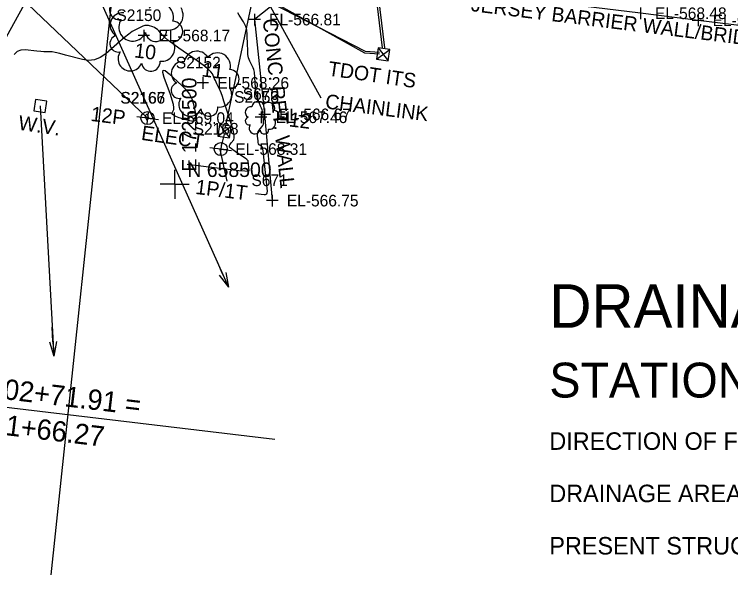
# Model space of a CAD drawing. Extents: x 1724534 to 1727318, y 657156 to 660047.
# Drawn here: x 1725444.8 to 1725691.4, y 658365.5 to 658558.5 of the extents above; entities that cross this region are included whole.
import ezdxf

# ---------------------------------------------------------------- set-up
doc = ezdxf.new("R2010")
doc.units = 0
for name, color, linetype in [('SURVEY - CENTERLINE - Preliminary Text', 7, 'Continuous'), ('SURVEY - CONTOURS - Intermediate with optional Text', 7, 'Continuous'), ('SURVEY - CONTROL - Grid', 7, 'Continuous'), ('SURVEY - CONTROL - Grid Text', 7, 'Continuous'), ('SURVEY - DRAINAGE - Area Shapes Text', 7, 'Continuous'), ('SURVEY - DRAINAGE - Storm Sewer', 7, 'Continuous'), ('SURVEY - DRAINAGE - Storm Sewer Text', 7, 'Continuous'), ('SURVEY - NON-TRANSPORTATION - Features', 7, 'Continuous'), ('SURVEY - NON-TRANSPORTATION - Features - Points - Elevations', 7, 'Continuous'), ('SURVEY - NON-TRANSPORTATION - Features - Points - Locators', 7, 'Continuous'), ('SURVEY - NON-TRANSPORTATION - Features - Points - Numbers', 7, 'Continuous'), ('SURVEY - NON-TRANSPORTATION - Features Text', 7, 'Continuous'), ('SURVEY - ROADSIDE BARRIERS - Points - Elevations', 7, 'Continuous'), ('SURVEY - ROADSIDE BARRIERS - Points - Locators', 7, 'Continuous'), ('SURVEY - ROADSIDE BARRIERS with Text', 7, 'Continuous'), ('SURVEY - UTILITIES - Electric (Underground) with Text', 7, 'Continuous'), ('SURVEY - UTILITIES - Fiber Optic Cable (Underground) with Text', 7, 'Continuous'), ('SURVEY - UTILITIES - Overhead Wire Crossings', 7, 'Continuous'), ('SURVEY - UTILITIES - Poles and Miscellaneous - Points - Elevations', 7, 'Continuous'), ('SURVEY - UTILITIES - Poles and Miscellaneous - Points - Locators', 7, 'Continuous'), ('SURVEY - UTILITIES - Poles and Miscellaneous - Points - Numbers', 7, 'Continuous'), ('SURVEY - UTILITIES - Poles and Miscellaneous with Text', 7, 'Continuous'), ('SURVEY - UTILITIES - Water with Text', 7, 'Continuous'), ('SURVEY - VEGETATION - Features - Points - Elevations', 7, 'Continuous'), ('SURVEY - VEGETATION - Features - Points - Locators', 7, 'Continuous'), ('SURVEY - VEGETATION - Features - Points - Numbers', 7, 'Continuous'), ('SURVEY - VEGETATION - Features with Text', 7, 'Continuous')]:
    doc.layers.add(name, color=color, linetype=linetype)

msp = doc.modelspace()

# ---------------------------------------------------------------- linework, layer by layer
at = {"layer": 'SURVEY - CENTERLINE - Preliminary Text'}
msp.add_line((1725332.93, 658436.26), (1725534.5, 658412.24), dxfattribs=at)
at = {"layer": 'SURVEY - CONTOURS - Intermediate with optional Text'}
for points in [[(1725527.79, 658496.86), (1725530.76, 658496.49), (1725531.31, 658496.5), (1725531.68, 658496.68), (1725531.88, 658497.04), (1725531.9, 658497.56), (1725530.43, 658511.53), (1725530.34, 658512.08), (1725530.22, 658512.51), (1725530.06, 658512.83), (1725529.86, 658513.03), (1725529.26, 658513.42), (1725529.06, 658513.62), (1725528.9, 658513.94), (1725528.77, 658514.37), (1725528.68, 658514.91), (1725528.49, 658516.51), (1725528.47, 658517.09), (1725528.56, 658517.63), (1725528.75, 658518.14), (1725529.05, 658518.6), (1725530, 658519.8), (1725530.3, 658520.25), (1725530.51, 658520.69), (1725530.61, 658521.14), (1725530.62, 658521.58), (1725530.4, 658523.86), (1725530.31, 658524.8), (1725530.25, 658525.12), (1725530.1, 658525.58), (1725529.88, 658526.18), (1725529.58, 658526.92), (1725528.68, 658529.07), (1725528.38, 658529.82), (1725528.15, 658530.48), (1725528.01, 658531.04), (1725527.94, 658531.51), (1725527.42, 658538.54), (1725527.35, 658539.03), (1725527.21, 658539.55), (1725527, 658540.12), (1725526.72, 658540.72), (1725525.89, 658542.39), (1725525.61, 658543), (1725525.41, 658543.58), (1725525.28, 658544.12), (1725525.22, 658544.63), (1725525.17, 658545.95), (1725525.14, 658546.45), (1725525.12, 658546.95), (1725525.1, 658547.47), (1725525.08, 658547.99), (1725525.02, 658549.39), (1725525, 658549.91), (1725524.97, 658550.45), (1725524.95, 658550.99), (1725524.93, 658551.55), (1725524.86, 658553.03), (1725524.77, 658553.62), (1725524.54, 658554.29), (1725524.18, 658555.04), (1725523.69, 658555.87), (1725522.19, 658558.17), (1725521.74, 658559.05)], [(1725504.32, 658506.95), (1725519.3, 658505.11), (1725522.1, 658504.78), (1725524.1, 658504.59), (1725525.3, 658504.54), (1725525.68, 658504.62), (1725525.33, 658508.01), (1725525.19, 658508.21), (1725524.83, 658508.54), (1725524.23, 658508.99), (1725523.39, 658509.56), (1725520.85, 658511.23), (1725520.01, 658511.8), (1725519.41, 658512.25), (1725519.04, 658512.57), (1725518.9, 658512.77), (1725518.86, 658513.15), (1725518.88, 658513.33), (1725518.99, 658513.57), (1725519.18, 658513.87), (1725519.46, 658514.25), (1725520.31, 658515.32), (1725520.5, 658515.95), (1725520.43, 658517.04), (1725520.1, 658518.59), (1725519.52, 658520.6), (1725517.61, 658526.57), (1725516.96, 658528.6), (1725516.4, 658530.23), (1725515.95, 658531.45), (1725515.61, 658532.27), (1725514.84, 658533.9), (1725514.56, 658534.52), (1725514.28, 658535.13), (1725514, 658535.74), (1725513.72, 658536.35), (1725513, 658537.97), (1725512.47, 658538.71), (1725511.41, 658539.71), (1725509.83, 658540.97), (1725507.72, 658542.5), (1725501.41, 658546.9), (1725499.28, 658548.42), (1725497.63, 658549.66), (1725496.45, 658550.62), (1725495.76, 658551.31), (1725494.53, 658552.78), (1725494.06, 658553.28), (1725493.56, 658553.68), (1725493.03, 658553.98), (1725492.47, 658554.19), (1725490.96, 658554.61), (1725490.37, 658554.69), (1725489.73, 658554.64), (1725489.04, 658554.46), (1725488.3, 658554.13), (1725486.26, 658553.09), (1725485.36, 658552.55), (1725484.2, 658551.71), (1725482.78, 658550.57), (1725481.1, 658549.14), (1725476.25, 658544.91), (1725474.39, 658543.59), (1725472.43, 658542.82), (1725470.38, 658542.6), (1725468.23, 658542.91), (1725462.39, 658544.48), (1725460.42, 658544.99), (1725458.91, 658545.35), (1725457.86, 658545.56), (1725457.27, 658545.62), (1725456.29, 658545.57), (1725455.78, 658545.58), (1725454.99, 658545.62), (1725453.9, 658545.71), (1725452.53, 658545.84), (1725448.48, 658546.23), (1725447.06, 658546.16), (1725445.81, 658545.66), (1725444.74, 658544.71)], [(1725496.39, 658536.76), (1725495.9, 658538.47), (1725496.02, 658539.26), (1725496.74, 658539.12), (1725498.07, 658538.06), (1725502.43, 658533.99), (1725503.9, 658532.47), (1725505.05, 658530.96), (1725505.87, 658529.45), (1725506.38, 658527.94), (1725507.29, 658523.94), (1725507.41, 658522.68), (1725507.11, 658521.9), (1725506.37, 658521.6), (1725505.2, 658521.78), (1725501.52, 658522.9), (1725500.34, 658523.32), (1725499.55, 658523.74), (1725499.15, 658524.17), (1725499.15, 658524.6), (1725499.68, 658525.74), (1725499.76, 658526.39), (1725499.58, 658527.48), (1725499.16, 658529), (1725498.5, 658530.95), (1725496.39, 658536.76)], [(1725490.89, 658522.57), (1725490.95, 658522.75), (1725490.97, 658522.93), (1725490.96, 658523.12), (1725490.91, 658523.31), (1725490.73, 658523.82), (1725490.65, 658523.97), (1725490.55, 658524.05), (1725490.44, 658524.05), (1725490.3, 658523.98), (1725489.93, 658523.69), (1725489.82, 658523.56), (1725489.78, 658523.39), (1725489.81, 658523.19), (1725489.9, 658522.95), (1725490.25, 658522.26), (1725490.37, 658522.06), (1725490.48, 658521.96), (1725490.58, 658521.98), (1725490.67, 658522.1), (1725490.89, 658522.57)]]:
    msp.add_lwpolyline(points, dxfattribs=at)
at = {"layer": 'SURVEY - CONTROL - Grid'}
for q in [(1725500, 658505), (1725495, 658500), (1725505, 658500), (1725500, 658495)]:
    msp.add_line((1725500, 658500), q, dxfattribs=at)
at = {"layer": 'SURVEY - DRAINAGE - Storm Sewer'}
for p, q in [((1725462.98, 658588.87), (1725518.53, 658464.57)), ((1725516.49, 658469.14), (1725514.45, 658473.7)), ((1725515.35, 658468.63), (1725518.53, 658464.57)), ((1725516.49, 658469.14), (1725518.53, 658464.57)), ((1725516.49, 658469.14), (1725518.53, 658464.57)), ((1725517.63, 658469.65), (1725518.53, 658464.57))]:
    msp.add_line(p, q, dxfattribs=at)
at = {"layer": 'SURVEY - DRAINAGE - Storm Sewer Text'}
msp.add_line((1725436.6, 658540.79), (1725462.98, 658588.87), dxfattribs=at)
at = {"layer": 'SURVEY - NON-TRANSPORTATION - Features'}
msp.add_lwpolyline([(1725539.44, 658572.34), (1725532.93, 658561.06), (1725527.49, 658556.7)], dxfattribs=at)
at = {"layer": 'SURVEY - NON-TRANSPORTATION - Features - Points - Locators'}
for p, q in [((1725527.49, 658558.7), (1725527.49, 658554.7)), ((1725527.49, 658558.7), (1725527.49, 658554.7)), ((1725529.49, 658556.7), (1725525.49, 658556.7)), ((1725529.49, 658556.7), (1725525.49, 658556.7)), ((1725530.93, 658526.05), (1725530.93, 658522.05)), ((1725532.93, 658524.05), (1725528.93, 658524.05)), ((1725533.59, 658496.36), (1725533.59, 658492.36)), ((1725535.59, 658494.36), (1725531.59, 658494.36))]:
    msp.add_line(p, q, dxfattribs=at)
at = {"layer": 'SURVEY - NON-TRANSPORTATION - Features Text'}
msp.add_line((1725532.93, 658561.06), (1725550.31, 658529.75), dxfattribs=at)
at = {"layer": 'SURVEY - ROADSIDE BARRIERS - Points - Locators'}
for p, q in [((1725660.28, 658560.86), (1725660.28, 658556.86)), ((1725682.13, 658556.43), (1725678.13, 658556.43)), ((1725680.13, 658558.43), (1725680.13, 658554.43))]:
    msp.add_line(p, q, dxfattribs=at)
at = {"layer": 'SURVEY - ROADSIDE BARRIERS with Text'}
for points in [[(1725762.72, 658545.48), (1725760.68, 658546.18), (1725739.67, 658549.03), (1725719.83, 658551.53), (1725699.98, 658553.97), (1725680.13, 658556.43), (1725660.28, 658558.86), (1725640.43, 658561.3), (1725620.59, 658563.76), (1725600.74, 658566.22), (1725580.89, 658568.65), (1725561.04, 658571.09), (1725541.17, 658573.41), (1725539.63, 658573.41), (1725538.14, 658573.13)], [(1725527.49, 658556.7), (1725530.93, 658524.05), (1725533.59, 658494.36)]]:
    msp.add_lwpolyline(points, dxfattribs=at)
at = {"layer": 'SURVEY - UTILITIES - Electric (Underground) with Text'}
for p, q in [((1725526.16, 658561.18), (1725517.23, 658519.23)), ((1725517.04, 658517.25), (1725515.97, 658513.06))]:
    msp.add_line(p, q, dxfattribs=at)
for points in [[(1725557.51, 658671.14), (1725558.43, 658655.23), (1725571.36, 658547)], [(1725570.47, 658545.32), (1725565.67, 658545.65), (1725533.36, 658562.34), (1725527.6, 658562.48)]]:
    msp.add_lwpolyline(points, dxfattribs=at)
at = {"layer": 'SURVEY - UTILITIES - Fiber Optic Cable (Underground) with Text'}
for points in [[(1725558.07, 658671.32), (1725558.96, 658656.48), (1725572.24, 658547)], [(1725570.54, 658544.83), (1725565.5, 658545.17), (1725533.56, 658562.95), (1725528.58, 658563.31), (1725528.95, 658565.81)]]:
    msp.add_lwpolyline(points, dxfattribs=at)
at = {"layer": 'SURVEY - UTILITIES - Overhead Wire Crossings'}
for p, q in [((1725512.62, 658889.98), (1725457.38, 658365.55)), ((1725320.87, 658684.66), (1725490.65, 658522.77))]:
    msp.add_line(p, q, dxfattribs=at)
at = {"layer": 'SURVEY - UTILITIES - Poles and Miscellaneous - Points - Locators'}
for p, q in [((1725490.89, 658524.75), (1725490.41, 658520.78)), ((1725492.64, 658522.52), (1725488.67, 658523.01)), ((1725517.84, 658511.87), (1725513.87, 658512.35)), ((1725516.1, 658514.09), (1725515.61, 658510.12))]:
    msp.add_line(p, q, dxfattribs=at)
at = {"layer": 'SURVEY - UTILITIES - Poles and Miscellaneous with Text'}
for p, q in [((1725569.51, 658543.01), (1725574.04, 658546.4)), ((1725570.08, 658546.97), (1725573.47, 658542.44)), ((1725571.77, 658544.7), (1725571.77, 658544.7)), ((1725490.65, 658522.77), (1725486.93, 658523.22)), ((1725490.65, 658522.77), (1725494.37, 658522.31)), ((1725514.88, 658516.59), (1725519.41, 658519.97)), ((1725515.45, 658520.55), (1725518.84, 658516.01)), ((1725517.15, 658518.28), (1725517.15, 658518.28)), ((1725515.85, 658512.11), (1725512.13, 658512.56)), ((1725515.57, 658511.97), (1725517.91, 658501.05)), ((1725515.85, 658512.11), (1725519.58, 658511.65))]:
    msp.add_line(p, q, dxfattribs=at)
for points in [[(1725570.08, 658546.97), (1725569.51, 658543.01), (1725573.47, 658542.44), (1725574.04, 658546.4), (1725570.08, 658546.97)], [(1725515.45, 658520.55), (1725514.88, 658516.59), (1725518.84, 658516.01), (1725519.41, 658519.97), (1725515.45, 658520.55)]]:
    msp.add_lwpolyline(points, dxfattribs=at)
for centre in [(1725490.65, 658522.77), (1725515.85, 658512.11)]:
    msp.add_circle(centre, 2.25, dxfattribs=at)
at = {"layer": 'SURVEY - UTILITIES - Water with Text'}
for p, q in [((1725453.74, 658526.97), (1725453.74, 658526.97)), ((1725453.74, 658526.97), (1725458.36, 658440.78)), ((1725458.09, 658445.77), (1725457.82, 658450.77)), ((1725456.88, 658445.71), (1725458.36, 658440.78)), ((1725458.09, 658445.77), (1725458.36, 658440.78)), ((1725458.09, 658445.77), (1725458.36, 658440.78)), ((1725459.3, 658445.84), (1725458.36, 658440.78))]:
    msp.add_line(p, q, dxfattribs=at)
msp.add_lwpolyline([(1725452.05, 658529.23), (1725451.48, 658525.27), (1725455.44, 658524.7), (1725456.01, 658528.66), (1725452.05, 658529.23)], dxfattribs=at)
at = {"layer": 'SURVEY - VEGETATION - Features - Points - Locators'}
for p, q in [((1725491.38, 658551.2), (1725487.38, 658551.2)), ((1725489.38, 658553.2), (1725489.38, 658549.2)), ((1725509.68, 658536.88), (1725509.68, 658532.88)), ((1725511.68, 658534.88), (1725507.68, 658534.88)), ((1725529.73, 658525.06), (1725529.73, 658521.06)), ((1725531.73, 658523.06), (1725527.73, 658523.06))]:
    msp.add_line(p, q, dxfattribs=at)
at = {"layer": 'SURVEY - VEGETATION - Features with Text'}
for centre, radius in [((1725489.58, 658551.28), 0.147), ((1725509.86, 658534.95), 0.137), ((1725529.83, 658523.1), 0.0685)]:
    msp.add_circle(centre, radius, dxfattribs=at)
for centre, radius, start, end in [((1725480.84, 658559.94), 3.27, 105.0317, 283.7773), ((1725494.82, 658557.51), 4.76, 342.8641, 138.7026), ((1725481.96, 658554.81), 4.21, 82.9155, 239.7044), ((1725497.76, 658558.18), 5.13, 262.9581, 29.8037), ((1725485.52, 658554.04), 4.76, 145.0523, 338.472), ((1725499.25, 658552.6), 3.51, 273.117, 88.1173), ((1725493.53, 658552.77), 3.62, 187.671, 4.9902), ((1725480.58, 658548.4), 2.89, 105.0317, 283.7773), ((1725495.52, 658546.84), 4.52, 262.9581, 29.8037), ((1725484.71, 658543.19), 4.2, 145.0523, 338.472), ((1725507.62, 658541.33), 4.47, 31.9683, 169.4925), ((1725514.76, 658540.77), 4.44, 342.8641, 138.7026), ((1725491.78, 658542.07), 3.19, 187.671, 4.9902), ((1725502.75, 658538.25), 3.92, 82.9155, 239.7044), ((1725518.89, 658536.18), 3.28, 273.117, 88.1173), ((1725501.47, 658532.26), 2.69, 105.0317, 283.7773), ((1725515.41, 658530.81), 4.22, 262.9581, 29.8037), ((1725505.32, 658527.4), 3.92, 145.0523, 338.472), ((1725511.92, 658526.36), 2.98, 187.671, 4.9902), ((1725526.27, 658524.75), 1.96, 82.9155, 239.7044), ((1725528.71, 658526.29), 2.24, 31.9683, 169.4925), ((1725532.27, 658526), 2.22, 342.8641, 138.7026), ((1725534.34, 658523.71), 1.64, 273.117, 88.1173), ((1725525.63, 658521.75), 1.35, 105.0317, 283.7773), ((1725532.6, 658521.03), 2.11, 262.9581, 29.8037), ((1725527.56, 658519.32), 1.96, 145.0523, 338.472), ((1725530.85, 658518.8), 1.49, 187.671, 4.9902)]:
    msp.add_arc(centre, radius, start, end, dxfattribs=at)

# ---------------------------------------------------------------- texts
at = {"layer": 'SURVEY - CENTERLINE - Preliminary Text'}
for s, p in [('MURPHY ROAD STA. 102+71.91 =', (1725340.19, 658438.04)), ('I-440 OFF RAMP STA. 21+66.27', (1725338.74, 658425.87))]:
    msp.add_text(s, height=7, rotation=353.2033, dxfattribs=at).set_placement(p)
at = {"layer": 'SURVEY - CONTROL - Grid Text'}
msp.add_text(' E 1725500 ', height=5, rotation=90, dxfattribs=at).set_placement((1725507.5, 658502.5))
msp.add_text(' N 658500 ', height=5, dxfattribs=at).set_placement((1725502.5, 658502.5))
at = {"layer": 'SURVEY - DRAINAGE - Area Shapes Text'}
for s, height, p in [('DRAINAGE DATA FOR PIPE', 15, (1725628.96, 658450.56)), ('STATION 103+01.90           ', 12, (1725628.96, 658426.56)), ('DIRECTION OF FLOW LEFT                   ', 6.0198, (1725628.96, 658408.54)), ('DRAINAGE AREA 0.299 AC        ROLLING', 6.0198, (1725628.96, 658390.52)), ('PRESENT STRUCTURE: 18"RCP                      ', 6.0198, (1725628.96, 658372.5))]:
    msp.add_text(s, height=height, dxfattribs=at).set_placement(p)
at = {"layer": 'SURVEY - NON-TRANSPORTATION - Features - Points - Elevations'}
for s, p in [('EL-566.81', (1725532.49, 658554.7)), ('EL-566.81', (1725532.49, 658554.7)), ('EL-566.67', (1725535.93, 658522.05)), ('EL-566.75', (1725538.59, 658492.36))]:
    msp.add_text(s, height=4, dxfattribs=at).set_placement(p)
at = {"layer": 'SURVEY - NON-TRANSPORTATION - Features - Points - Numbers'}
for s, p in [('S670', (1725523.42, 658529.05)), ('S671', (1725526.41, 658499.36))]:
    msp.add_text(s, height=4, dxfattribs=at).set_placement(p)
at = {"layer": 'SURVEY - NON-TRANSPORTATION - Features Text'}
msp.add_text('CHAINLINK', height=5, rotation=352.8338, dxfattribs=at).set_placement((1725551.6, 658526.13))
at = {"layer": 'SURVEY - ROADSIDE BARRIERS - Points - Elevations'}
for s, p in [('EL-568.48', (1725665.28, 658556.86)), ('EL-568.77', (1725685.13, 658554.43))]:
    msp.add_text(s, height=4, dxfattribs=at).set_placement(p)
at = {"layer": 'SURVEY - ROADSIDE BARRIERS with Text'}
for s, rotation, p in [('JERSEY BARRIER WALL/BRIDGE', 352.94, (1725601.83, 658559.64)), ('CONC. RET. WALL', 276.0056, (1725530.3, 658556.78))]:
    msp.add_text(s, height=5, rotation=rotation, dxfattribs=at).set_placement(p)
at = {"layer": 'SURVEY - UTILITIES - Poles and Miscellaneous - Points - Elevations'}
for s, p in [('EL-569.04', (1725495.65, 658520.77)), ('EL-569.04', (1725495.65, 658520.77)), ('EL-568.31', (1725520.85, 658510.11))]:
    msp.add_text(s, height=4, dxfattribs=at).set_placement(p)
at = {"layer": 'SURVEY - UTILITIES - Poles and Miscellaneous - Points - Numbers'}
for s, p in [('S2166', (1725481.25, 658527.77)), ('S2167', (1725481.36, 658527.77)), ('S2168', (1725506.52, 658517.11))]:
    msp.add_text(s, height=4, dxfattribs=at).set_placement(p)
at = {"layer": 'SURVEY - UTILITIES - Poles and Miscellaneous with Text'}
for s, rotation, p in [('TDOT ITS', 351.7546, (1725552.56, 658537.46)), ('12P', 352.8641, (1725470.9, 658521.83)), ('ELECT', 351.7546, (1725488.28, 658515.31)), ('1P/1T', 352.8641, (1725506.95, 658496.69))]:
    msp.add_text(s, height=5, rotation=rotation, dxfattribs=at).set_placement(p)
at = {"layer": 'SURVEY - UTILITIES - Water with Text'}
msp.add_text('W.V.', height=5, rotation=351.7546, dxfattribs=at).set_placement((1725445.94, 658518.8))
at = {"layer": 'SURVEY - VEGETATION - Features - Points - Elevations'}
for s, p in [('EL-568.17', (1725494.38, 658549.2)), ('EL-568.26', (1725514.68, 658532.88)), ('EL-567.46', (1725534.73, 658521.06))]:
    msp.add_text(s, height=4, dxfattribs=at).set_placement(p)
at = {"layer": 'SURVEY - VEGETATION - Features - Points - Numbers'}
for s, p in [('S2150', (1725479.92, 658556.2)), ('S2152', (1725500.39, 658539.88)), ('S2153', (1725520.45, 658528.06))]:
    msp.add_text(s, height=4, dxfattribs=at).set_placement(p)
at = {"layer": 'SURVEY - VEGETATION - Features with Text'}
for s, p in [('10', (1725485.88, 658543.71)), ('11', (1725509.1, 658537.15)), ('12', (1725539.16, 658519.93))]:
    msp.add_text(s, height=5, rotation=353.0264, dxfattribs=at).set_placement(p)

doc.saveas('drawing.dxf')
